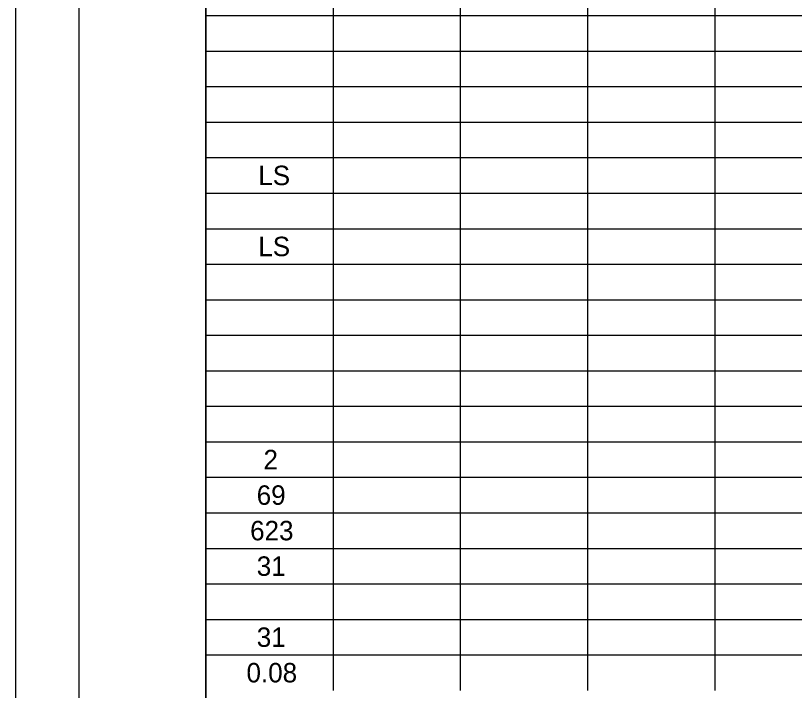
# Model space of a CAD drawing. Extents: x 0 to 34, y 0 to 22.
# Drawn here: x 0 to 6.14, y 11.42 to 16.74 of the extents above; entities that cross this region are included whole.
import ezdxf

# ---------------------------------------------------------------- set-up
doc = ezdxf.new("R2010")
doc.units = 0
for name, color, linetype in [('Default', 7, 'Continuous'), ('SH_Border', 7, 'Continuous'), ('SH_Cut_Line', 7, 'Continuous')]:
    doc.layers.add(name, color=color, linetype=linetype)

msp = doc.modelspace()

# ---------------------------------------------------------------- linework, layer by layer
at = {"layer": 'Default'}
for p, q in [((1.5, 17.02), (1.5, 16.74)), ((2.5025, 17.02), (2.5025, 16.74)), ((3.5051, 17.02), (3.5051, 16.74)), ((4.5076, 17.02), (4.5076, 16.74)), ((5.5101, 17.02), (5.5101, 16.74)), ((1.5, 16.74), (6.5126, 16.74)), ((1.5, 16.74), (1.5, 16.18)), ((2.5025, 16.74), (2.5025, 16.18)), ((3.5051, 16.74), (3.5051, 16.18)), ((4.5076, 16.74), (4.5076, 16.18)), ((5.5101, 16.74), (5.5101, 16.18)), ((1.5, 16.46), (6.5126, 16.46)), ((1.5, 16.18), (6.5126, 16.18)), ((1.5, 16.18), (1.5, 15.9)), ((2.5025, 16.18), (2.5025, 15.9)), ((3.5051, 16.18), (3.5051, 15.9)), ((4.5076, 16.18), (4.5076, 15.9)), ((5.5101, 16.18), (5.5101, 15.9)), ((1.5, 15.9), (6.5126, 15.9)), ((1.5, 15.9), (1.5, 15.62)), ((2.5025, 15.9), (2.5025, 15.62)), ((3.5051, 15.9), (3.5051, 15.62)), ((4.5076, 15.9), (4.5076, 15.62)), ((5.5101, 15.9), (5.5101, 15.62)), ((1.5, 15.62), (6.5126, 15.62)), ((1.5, 15.62), (1.5, 15.34)), ((2.5025, 15.62), (2.5025, 15.34)), ((3.5051, 15.62), (3.5051, 15.34)), ((4.5076, 15.62), (4.5076, 15.34)), ((5.5101, 15.62), (5.5101, 15.34)), ((1.5, 15.34), (6.5126, 15.34)), ((1.5, 15.34), (1.5, 14.78)), ((2.5025, 15.34), (2.5025, 14.78)), ((3.5051, 15.34), (3.5051, 14.78)), ((4.5076, 15.34), (4.5076, 14.78)), ((5.5101, 15.34), (5.5101, 14.78)), ((1.5, 15.06), (6.5126, 15.06)), ((1.5, 14.78), (6.5126, 14.78)), ((1.5, 14.78), (1.5, 14.5)), ((2.5025, 14.78), (2.5025, 14.5)), ((3.5051, 14.78), (3.5051, 14.5)), ((4.5076, 14.78), (4.5076, 14.5)), ((5.5101, 14.78), (5.5101, 14.5)), ((1.5, 14.5), (6.5126, 14.5)), ((1.5, 14.5), (1.5, 14.22)), ((2.5025, 14.5), (2.5025, 14.22)), ((3.5051, 14.5), (3.5051, 14.22)), ((4.5076, 14.5), (4.5076, 14.22)), ((5.5101, 14.5), (5.5101, 14.22)), ((1.5, 14.22), (6.5126, 14.22)), ((1.5, 14.22), (1.5, 13.94)), ((2.5025, 14.22), (2.5025, 13.94)), ((3.5051, 14.22), (3.5051, 13.94)), ((4.5076, 14.22), (4.5076, 13.94)), ((5.5101, 14.22), (5.5101, 13.94)), ((1.5, 13.94), (6.5126, 13.94)), ((1.5, 13.94), (1.5, 11.7)), ((2.5025, 13.94), (2.5025, 11.7)), ((3.5051, 13.94), (3.5051, 11.7)), ((4.5076, 13.94), (4.5076, 11.7)), ((5.5101, 13.94), (5.5101, 11.7)), ((1.5, 13.66), (6.5126, 13.66)), ((1.5, 13.38), (6.5126, 13.38)), ((1.5, 13.1), (6.5126, 13.1)), ((1.5, 12.82), (6.5126, 12.82)), ((1.5, 12.54), (6.5126, 12.54)), ((1.5, 12.26), (6.5126, 12.26)), ((1.5, 11.98), (6.5126, 11.98)), ((1.5, 11.7), (6.5126, 11.7)), ((1.5, 11.7), (1.5, 11.42)), ((2.5025, 11.7), (2.5025, 11.42)), ((3.5051, 11.7), (3.5051, 11.42)), ((4.5076, 11.7), (4.5076, 11.42)), ((5.5101, 11.7), (5.5101, 11.42))]:
    msp.add_line(p, q, dxfattribs=at)
at = {"layer": 'SH_Border'}
for points in [[(0.5, 21.5), (1.5, 21.5), (1.5, 0.5), (0.5, 0.5)], [(1.5, 21.5), (33.5, 21.5), (33.5, 0.5), (1.5, 0.5)]]:
    msp.add_lwpolyline(points, close=True, dxfattribs=at)
at = {"layer": 'SH_Cut_Line'}
msp.add_lwpolyline([(0, 0), (34, 0), (34, 22), (0, 22)], close=True, dxfattribs=at)

# ---------------------------------------------------------------- texts
at = {"layer": 'Default'}
for s, height, p in [('LS', 0.15333, (1.9129, 15.4033)), ('LS', 0.15333, (1.9129, 14.8433)), ('2', 0.1533, (1.954, 13.1633)), ('69', 0.15333, (1.9004, 12.8833)), ('623', 0.15333, (1.8484, 12.6033)), ('31', 0.15333, (1.9008, 12.3233)), ('31', 0.15333, (1.9008, 11.7633)), ('0.08', 0.15333, (1.8198, 11.4833))]:
    msp.add_text(s, height=height, dxfattribs=at).set_placement(p)

doc.saveas('drawing.dxf')
